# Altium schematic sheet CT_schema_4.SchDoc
size 573 x 363 mm
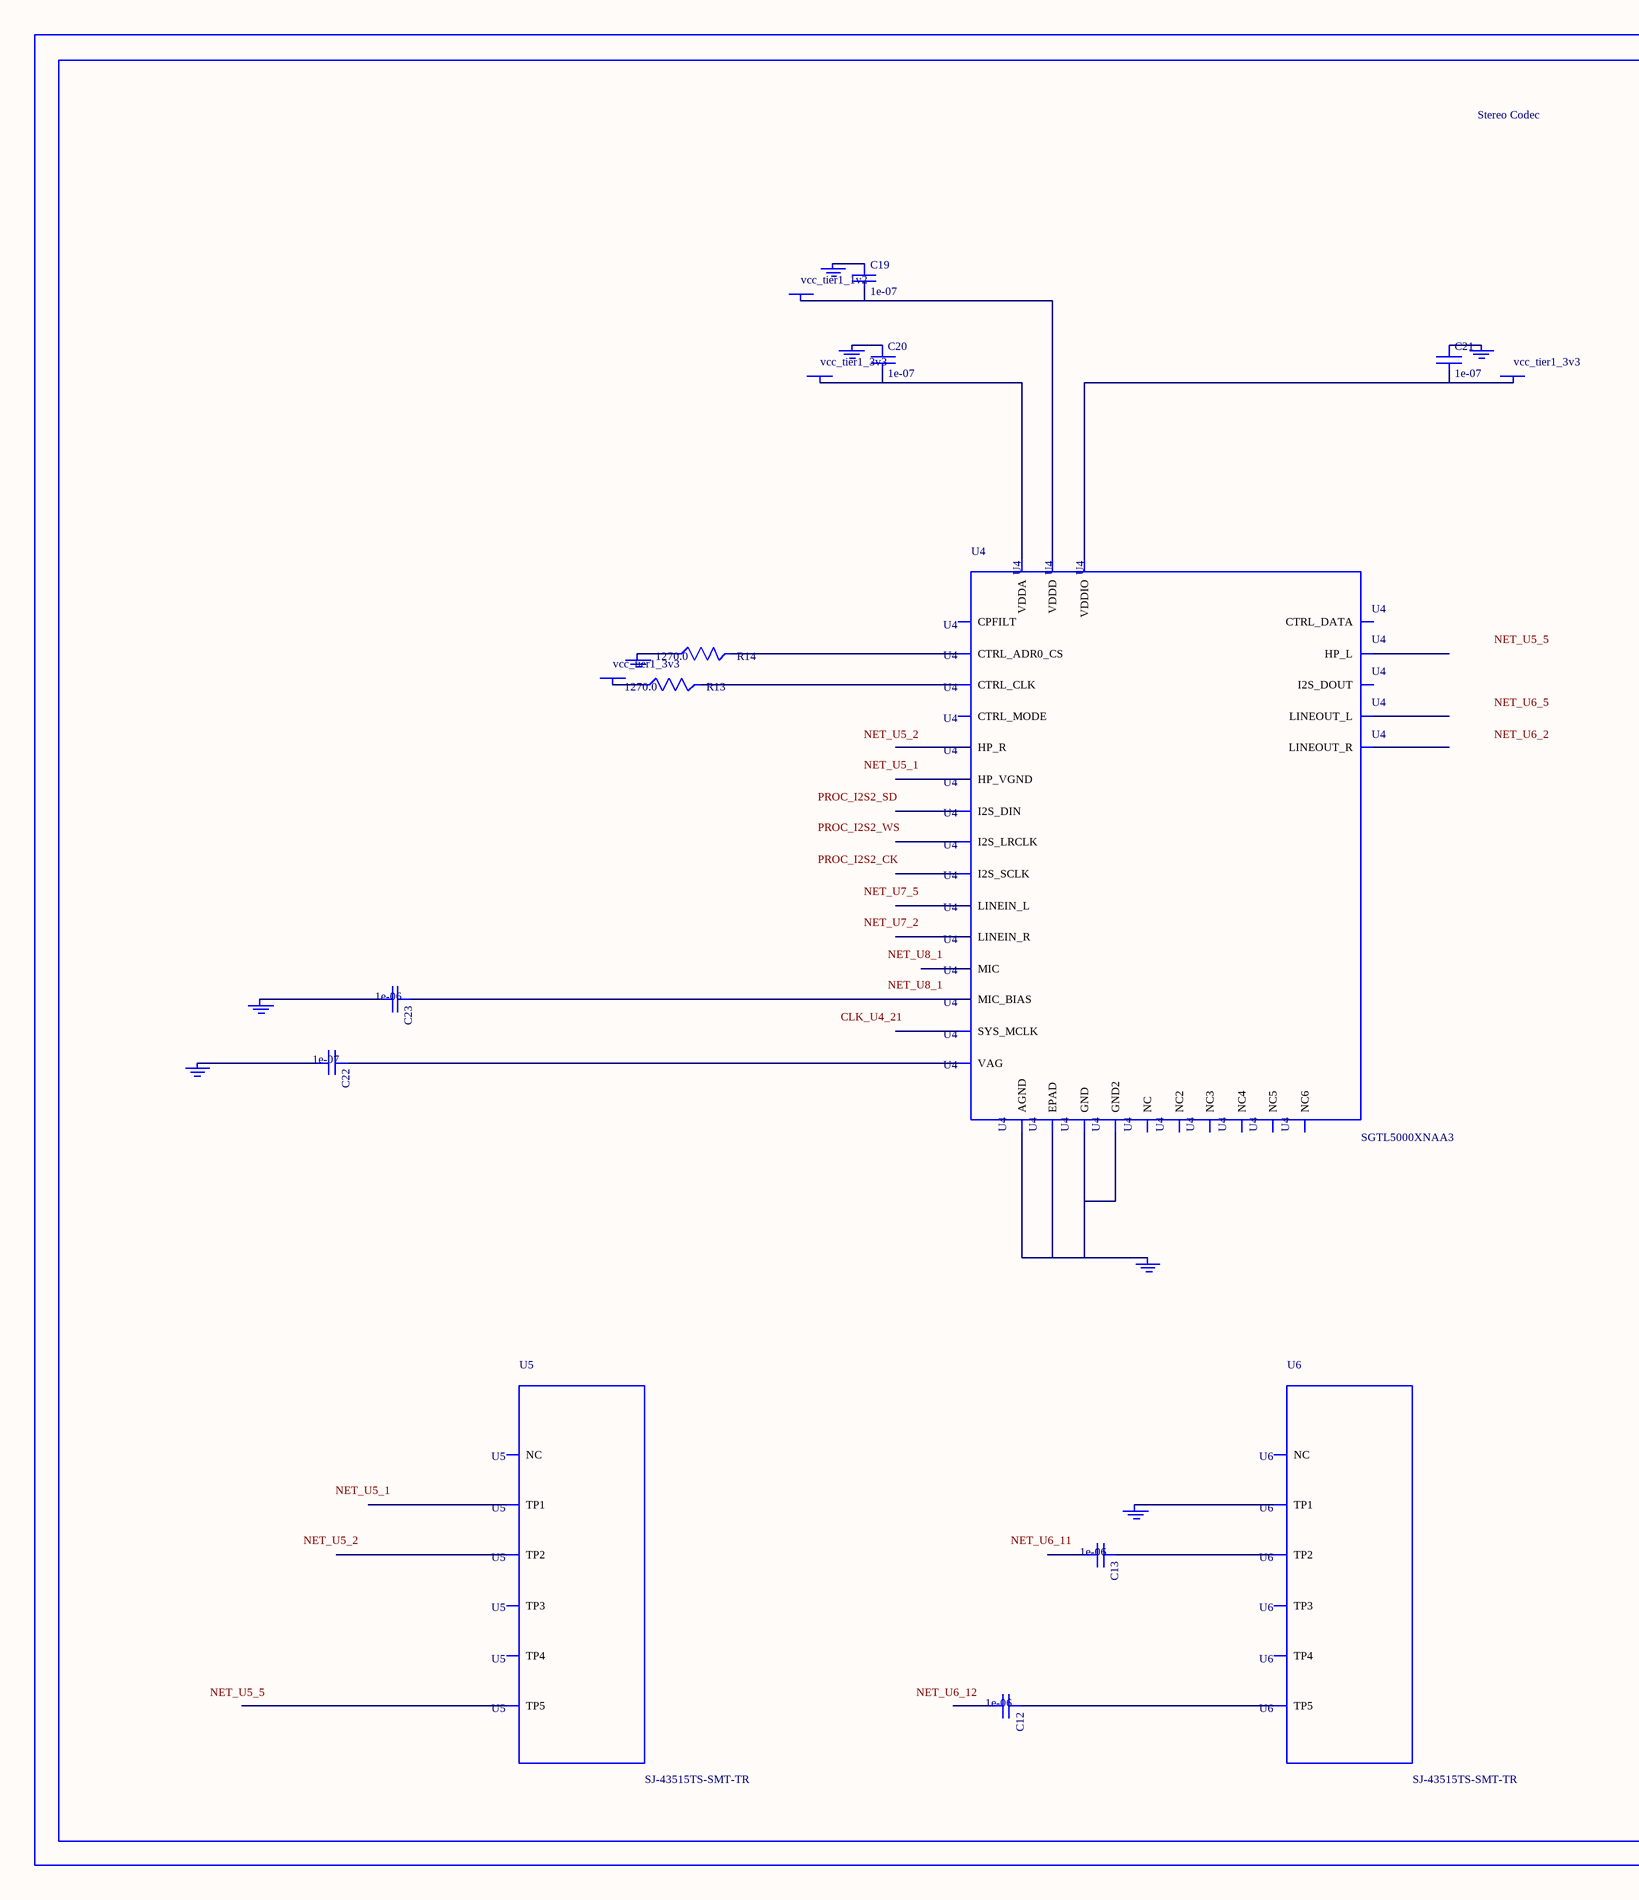
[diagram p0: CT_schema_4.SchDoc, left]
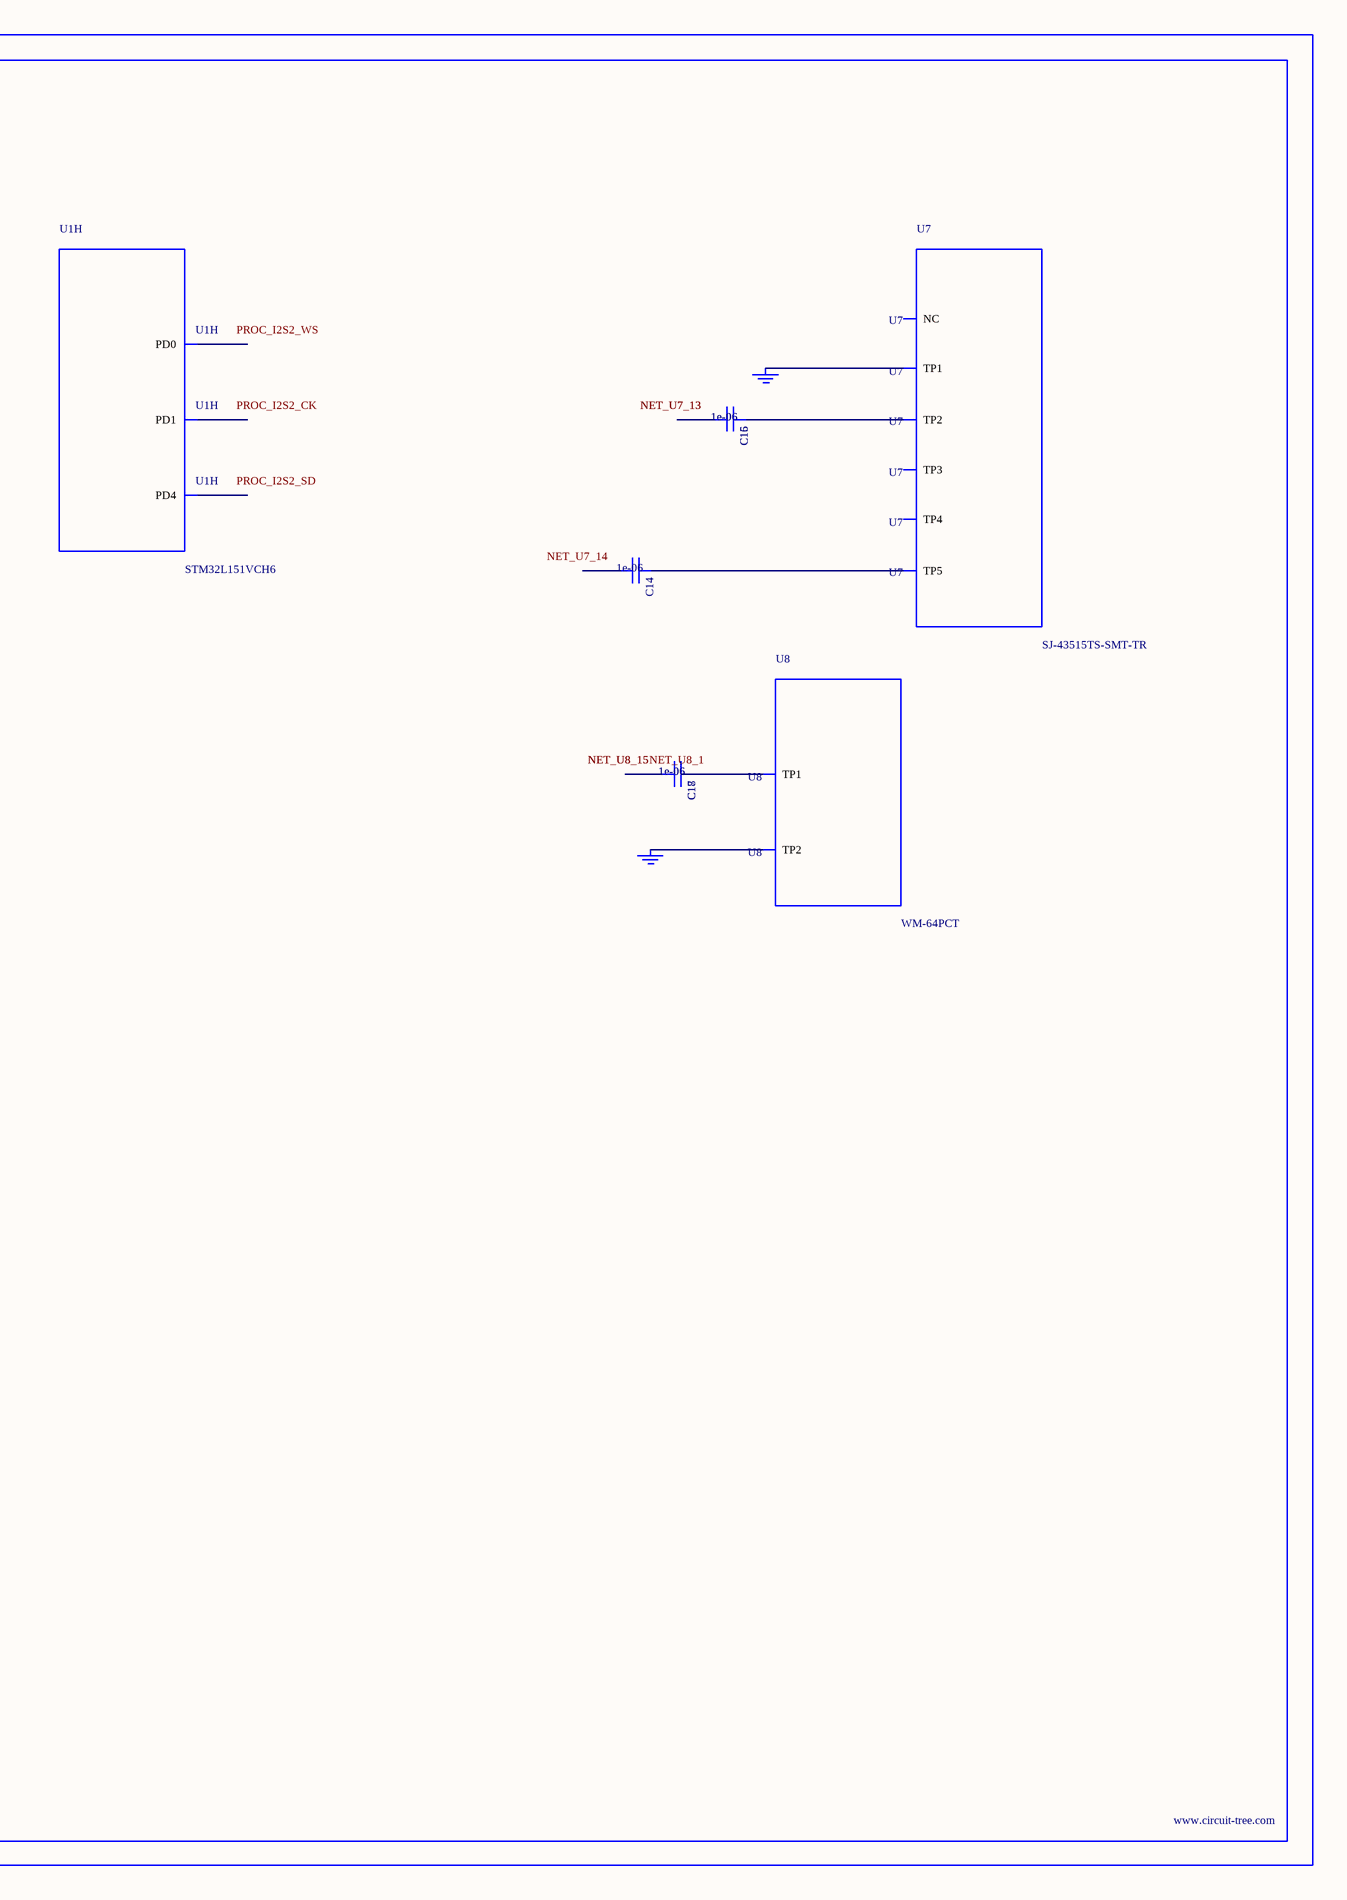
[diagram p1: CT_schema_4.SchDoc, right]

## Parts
BORDER3  (no value)
C12  1e-06  [C0603]
C13  1e-06  [C0603]
C14  1e-06  [C0603]
C15  1e-06  [C0603]
C16  1e-06  [C0603]
C17  1e-06  [C0603]
C18  1e-06  [C0603]
C19  1e-07  [C0402]
C20  1e-07  [C0402]
C21  1e-07  [C0402]
C22  1e-07  [C0402]
C23  1e-06  [C0603]
GND_INSTANCE_3_0  (no value)
GND_INSTANCE_3_1  (no value)
GND_INSTANCE_3_2  (no value)
GND_INSTANCE_3_3  (no value)
GND_INSTANCE_3_4  (no value)
GND_INSTANCE_3_5  (no value)
GND_INSTANCE_3_6  (no value)
GND_INSTANCE_3_7  (no value)
GND_INSTANCE_3_8  (no value)
GND_INSTANCE_3_9  (no value)
GND_INSTANCE_3_10  (no value)
POWER_INSTANCE_3_0  vcc_tier1_3v3
POWER_INSTANCE_3_1  vcc_tier1_3v3
POWER_INSTANCE_3_2  vcc_tier1_3v3
POWER_INSTANCE_3_3  vcc_tier1_1v2
R13  1270.0  [R0603]
R14  1270.0  [R0603]
U1  STM32L151VCH6  [UFBGA100]  (part H of 9)
U4  SGTL5000XNAA3  [QFN-32]
U5  SJ-43515TS-SMT-TR  [SJ-43515TS-SMT-TR]
U6  SJ-43515TS-SMT-TR  [SJ-43515TS-SMT-TR]
U7  SJ-43515TS-SMT-TR  [SJ-43515TS-SMT-TR]
U8  WM-64PCT  [WM-64PC]

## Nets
NetC12_1: C12.1 U6.5(TP5)
NetC13_1: C13.1 U6.2(TP2)
NetC14_1: C14.1 U7.5(TP5)
NetC15_1: C15.1 C16.1 U7.2(TP2)
NetC15_2: C15.2 C16.2
NetC17_1: C17.1 C18.1 U8.1(TP1)
NetC17_2: C17.2 C18.2
NetC19_1: C19.1 GND_INSTANCE_3_5.0(GND)
NetC19_2: C19.2 POWER_INSTANCE_3_3.0(PWR) U4.30(VDDD)
NetC20_1: C20.1 GND_INSTANCE_3_1.0(GND)
NetC20_2: C20.2 POWER_INSTANCE_3_0.0(PWR) U4.5(VDDA)
NetC21_1: C21.1 GND_INSTANCE_3_4.0(GND)
NetC21_2: C21.2 POWER_INSTANCE_3_1.0(PWR) U4.20(VDDIO)
NetC22_1: C22.1 U4.10(VAG)
NetC22_2: C22.2 GND_INSTANCE_3_2.0(GND)
NetC23_1: C23.1 U4.16(MIC_BIAS)
NetC23_2: C23.2 GND_INSTANCE_3_3.0(GND)
NetGND_INSTANCE_3_0_0: GND_INSTANCE_3_0.0(GND) U4.1(GND) U4.3(GND2) U4.7(AGND) U4.EXP(EPAD)
NetGND_INSTANCE_3_6_0: GND_INSTANCE_3_6.0(GND) R14.1
NetGND_INSTANCE_3_7_0: GND_INSTANCE_3_7.0(GND) U6.1(TP1)
NetGND_INSTANCE_3_8_0: GND_INSTANCE_3_8.0(GND) GND_INSTANCE_3_9.0(GND) U7.1(TP1)
NetGND_INSTANCE_3_10_0: GND_INSTANCE_3_10.0(GND) U8.2(TP2)
NetPOWER_INSTANCE_3_2_0: POWER_INSTANCE_3_2.0(PWR) R13.1
NetR13_2: R13.2 U4.29(CTRL_CLK)
NetR14_2: R14.2 U4.31(CTRL_ADR0_CS)

Not connected (* = marked no-connect by the designer): C12 2; C13 2; C14 2; U1 B7(PD4) B9(PD1) C9(PD0); U4 2(HP_R) 4(HP_VGND) 6(HP_L) 8(NC) 9(NC2) 11(LINEOUT_R) 12(LINEOUT_L) 13(LINEIN_R) 14(LINEIN_L) 15(MIC) 17(NC3) 18(CPFILT) 19(NC4) 21(SYS_MCLK) 22(NC5) 23(I2S_LRCLK) 24(I2S_SCLK) 25(I2S_DOUT) 26(I2S_DIN) 27(CTRL_DATA) 28(NC6) 32(CTRL_MODE); U5 1(TP1) 2(TP2) 3(TP3) 4(TP4) 5(TP5) 6(NC); U6 3(TP3) 4(TP4) 6(NC); U7 3(TP3) 4(TP4) 6(NC)

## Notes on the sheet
- Labels drawn without touching a wire or pin: CLK_U4_21, NET_U5_1, NET_U5_2, NET_U5_5, NET_U6_2, NET_U6_5, NET_U6_11, NET_U6_12, NET_U7_2, NET_U7_5, NET_U7_14, NET_U8_1, PROC_I2S2_CK, PROC_I2S2_SD, PROC_I2S2_WS

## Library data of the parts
BORDER3 = BORDER_PAGE3
C12-C18 C23 = C0603C105K3RACTU
C19-C22 = C0402C104K3RACTU
GND_INSTANCE_3_0-GND_INSTANCE_3_10 = GND
POWER_INSTANCE_3_0-POWER_INSTANCE_3_3 = PWR
R13 R14 = RC0603FR-071K27L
